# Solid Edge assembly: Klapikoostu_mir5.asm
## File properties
Author: Türk
Template: Iso Assembly.asm
Last saved by: Türk
Revision: 3
Application: Solid Edge
Username: Türk
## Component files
Klapipuks.par
Klapp.par
Klapi vedru_mir1.par
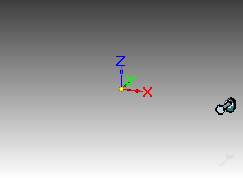
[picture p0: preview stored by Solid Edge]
